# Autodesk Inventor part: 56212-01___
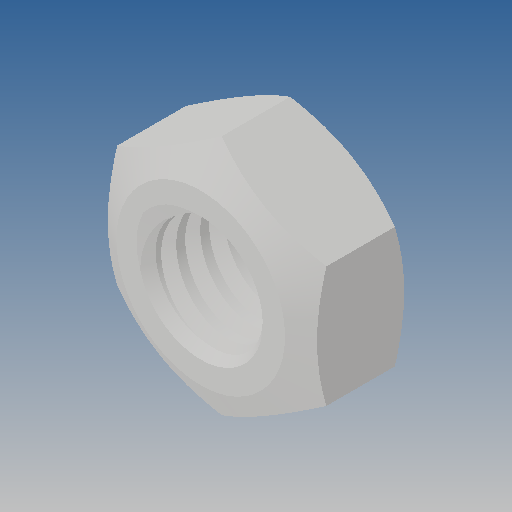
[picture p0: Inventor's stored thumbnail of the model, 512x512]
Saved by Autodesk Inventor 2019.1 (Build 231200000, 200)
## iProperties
Created: 2010-06
Part Number: 56212-01___
Material: Ogólny
Document SubType Name: Modeling
Designer: CADENGINEERING4
Density: 1 g/cm^3
Appearance: Domyślna
Author: CADENGINEERING4
Revision Number: ANY
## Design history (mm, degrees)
feature "NONE"
node "Bryła1"
